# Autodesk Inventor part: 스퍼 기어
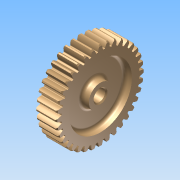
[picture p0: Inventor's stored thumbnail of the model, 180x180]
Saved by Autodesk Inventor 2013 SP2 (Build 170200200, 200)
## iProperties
Created: 2025-10
Part Number: 스퍼 기어
Material: Generic
Document SubType Name: Modeling
Designer: 601
Density: 1 g/cm^3
Author: 601
변환 표준: STEP AP214IS
전처리기: Build: 200, Release: 2013 SP2 Update 6 - Date: Thu 07/17/2014
전송 단위: 밀리미터
불확실성: 0.01
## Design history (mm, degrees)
node "스퍼 기어1"
node "솔리드1"
node "기준1"
